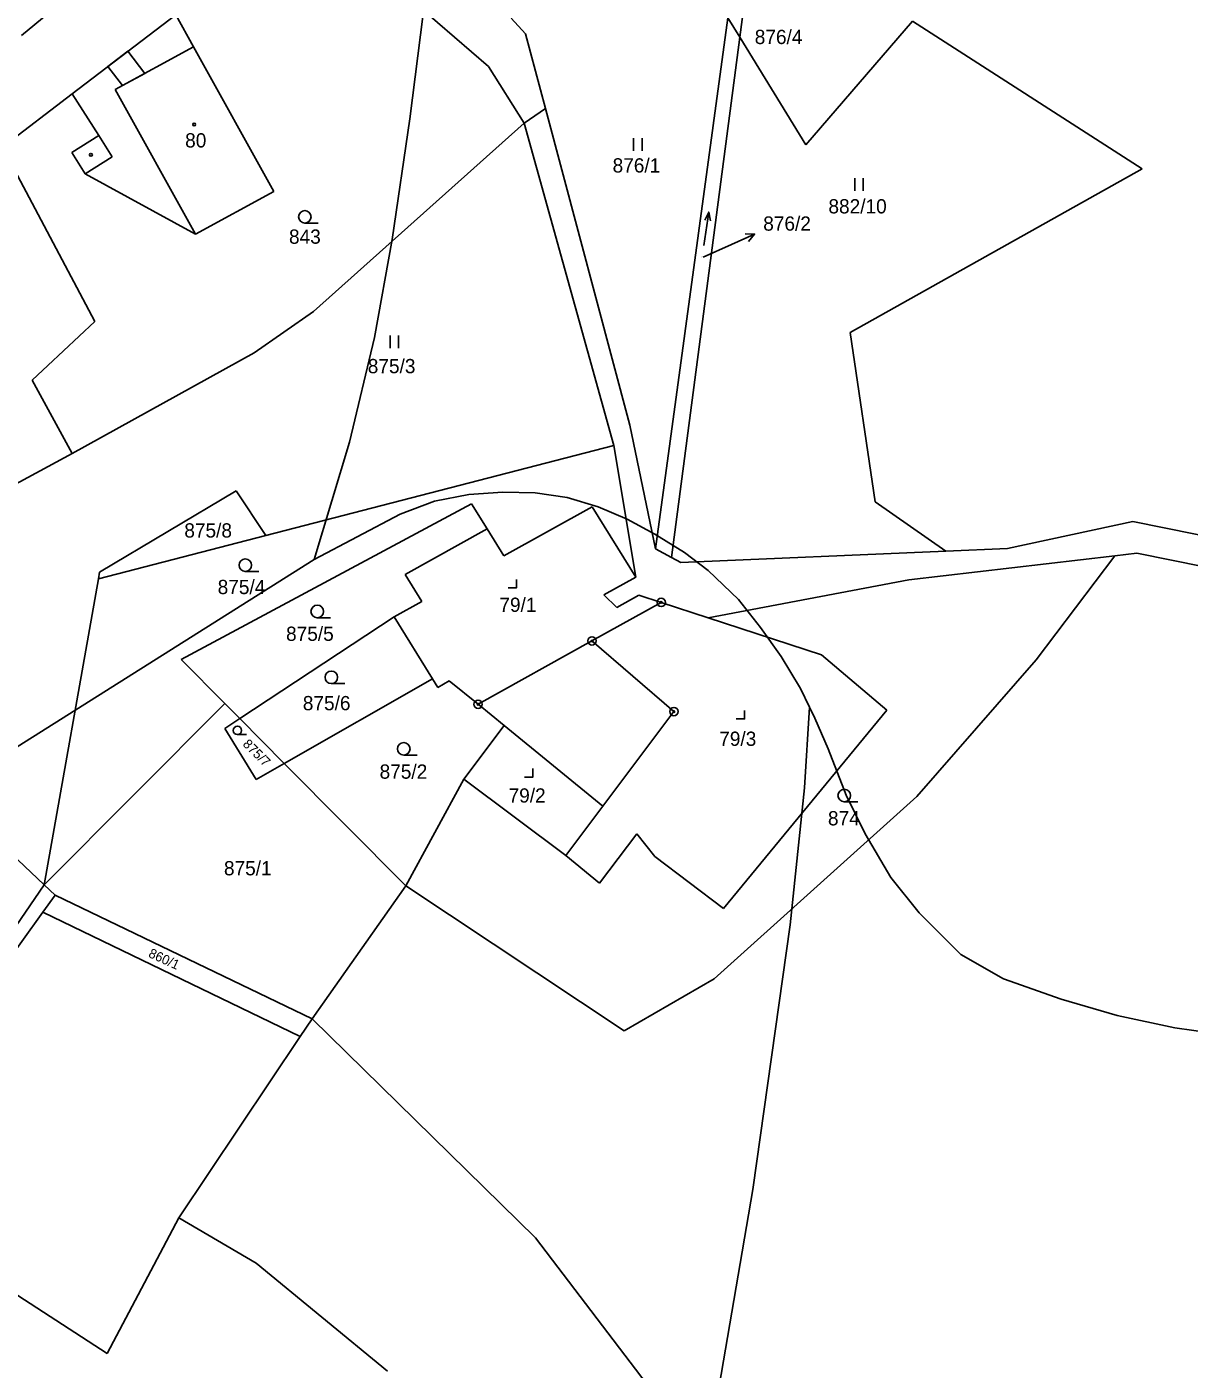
# Model space of a CAD drawing. Extents: x -546762 to -540209, y -1046851 to -1035694.
# Drawn here: x -543897 to -543758.3, y -1042074.7 to -1041914.5 of the extents above; entities that cross this region are included whole.
import ezdxf

# ---------------------------------------------------------------- set-up
doc = ezdxf.new("R2010")
doc.units = 0
for name, color, linetype in [('Vrstva 1', 7, 'Continuous'), ('Vrstva 16', 7, 'Continuous'), ('Vrstva 18', 7, 'Continuous'), ('Vrstva 19', 7, 'Continuous'), ('Vrstva 24', 7, 'Continuous'), ('Vrstva 25', 7, 'Continuous'), ('Vrstva 3', 7, 'Continuous'), ('Vrstva 30', 7, 'Continuous'), ('Vrstva 37', 7, 'Continuous'), ('Vrstva 4', 7, 'Continuous'), ('Vrstva 52', 7, 'Continuous'), ('Vrstva 6', 7, 'Continuous')]:
    doc.layers.add(name, color=color, linetype=linetype)

msp = doc.modelspace()

# ---------------------------------------------------------------- linework, layer by layer
at = {"layer": 'Vrstva 1'}
for p, q in [((-543811.96, -1041915.75), (-543810.7, -1041906.17)), ((-543813.38, -1041913.44), (-543822.02, -1041976.78)), ((-543813.38, -1041913.44), (-543811.96, -1041915.75)), ((-543804.07, -1041928.59), (-543791.36, -1041913.82)), ((-543763.94, -1041931.44), (-543791.36, -1041913.82)), ((-543820.11, -1041977.82), (-543811.96, -1041915.75)), ((-543811.96, -1041915.75), (-543804.07, -1041928.59))]:
    msp.add_line(p, q, dxfattribs=at)
for points in [[(-543847.79, -1041874.33), (-543897.64, -1041915.53)], [(-543841.93, -1041919.22), (-543852.08, -1041910.45)], [(-543879.25, -1041913.07), (-543891.6, -1041922.49)], [(-543877.12, -1041916.9), (-543879.25, -1041913.07)], [(-543837.53, -1041915.32), (-543839.22, -1041913.48)], [(-543837.53, -1041915.32), (-543835.15, -1041924.24)], [(-543877.12, -1041916.9), (-543867.53, -1041934.15)], [(-543841.93, -1041919.22), (-543837.7, -1041926.02)], [(-543891.6, -1041922.49), (-543899.92, -1041928.85)], [(-543891.6, -1041922.49), (-543888.44, -1041927.49)], [(-543837.7, -1041926.02), (-543835.15, -1041924.24)], [(-543835.15, -1041924.24), (-543825.08, -1041962.04)], [(-543837.7, -1041926.02), (-543862.8, -1041948.46)], [(-543826.99, -1041964.46), (-543837.7, -1041926.02)], [(-543888.44, -1041927.49), (-543891.66, -1041929.52)], [(-543888.91, -1041949.67), (-543899.92, -1041928.85)], [(-543891.66, -1041929.52), (-543890.05, -1041932.06)], [(-543890.05, -1041932.06), (-543876.88, -1041939.23)], [(-543867.53, -1041934.15), (-543876.88, -1041939.23)], [(-543888.91, -1041949.67), (-543896.39, -1041956.67)], [(-543862.8, -1041948.46), (-543869.88, -1041953.41)], [(-543869.88, -1041953.41), (-543891.62, -1041965.43)], [(-543896.39, -1041956.67), (-543891.62, -1041965.43)], [(-543825.08, -1041962.04), (-543822.02, -1041976.78)], [(-543826.99, -1041964.46), (-543868.49, -1041975.19)], [(-543824.36, -1041980.17), (-543826.99, -1041964.46)], [(-543891.62, -1041965.43), (-543922.35, -1041982.05)], [(-543872.05, -1041969.89), (-543888.34, -1041979.59)], [(-543872.05, -1041969.89), (-543868.49, -1041975.19)], [(-543878.6, -1041990), (-543843.97, -1041971.41)], [(-543843.97, -1041971.41), (-543842.1, -1041974.43)], [(-543840.11, -1041977.64), (-543829.56, -1041971.77)], [(-543829.56, -1041971.77), (-543824.36, -1041980.17)], [(-543780.03, -1041976.76), (-543765.06, -1041973.55)], [(-543765.06, -1041973.55), (-543735.36, -1041979.55)], [(-543868.49, -1041975.19), (-543888.48, -1041980.36)], [(-543851.87, -1041979.87), (-543842.1, -1041974.43)], [(-543842.1, -1041974.43), (-543840.11, -1041977.64)], [(-543820.11, -1041977.82), (-543822.02, -1041976.78)], [(-543818.99, -1041978.42), (-543787.37, -1041977.07)], [(-543787.37, -1041977.07), (-543780.03, -1041976.76)], [(-543818.99, -1041978.42), (-543820.11, -1041977.82)], [(-543767.21, -1041977.62), (-543791.8, -1041980.48)], [(-543776.58, -1041990.04), (-543767.21, -1041977.62)], [(-543764.58, -1041977.32), (-543767.21, -1041977.62)], [(-543764.58, -1041977.32), (-543736.23, -1041983.05)], [(-543894.94, -1042016.9), (-543888.48, -1041980.36)], [(-543888.48, -1041980.36), (-543888.34, -1041979.59)], [(-543849.89, -1041983.08), (-543851.87, -1041979.87)], [(-543824.36, -1041980.17), (-543828.16, -1041982.29)], [(-543791.8, -1041980.48), (-543815.73, -1041985.02)], [(-543853.2, -1041984.92), (-543849.89, -1041983.08)], [(-543829.59, -1041987.79), (-543821.33, -1041983.19)], [(-543826.62, -1041983.78), (-543828.16, -1041982.29)], [(-543823.99, -1041982.32), (-543826.62, -1041983.78)], [(-543821.33, -1041983.19), (-543823.99, -1041982.32)], [(-543815.73, -1041985.02), (-543821.33, -1041983.19)], [(-543871.61, -1041997.05), (-543853.2, -1041984.92)], [(-543853.2, -1041984.92), (-543848.62, -1041992.33)], [(-543815.73, -1041985.02), (-543802.2, -1041989.44)], [(-543843.18, -1041995.35), (-543829.59, -1041987.79)], [(-543829.59, -1041987.79), (-543819.81, -1041996.22)], [(-543878.6, -1041990), (-543873.39, -1041995.26)], [(-543802.2, -1041989.44), (-543794.42, -1041996.03)], [(-543790.82, -1042006.37), (-543776.58, -1041990.04)], [(-543921.63, -1041991.59), (-543894.94, -1042016.9)], [(-543866.3, -1042002.41), (-543848.62, -1041992.33)], [(-543848, -1041993.33), (-543848.62, -1041992.33)], [(-543846.61, -1041992.56), (-543848, -1041993.33)], [(-543846.61, -1041992.56), (-543843.18, -1041995.35)], [(-543894.94, -1042016.9), (-543873.39, -1041995.26)], [(-543873.39, -1041995.26), (-543871.61, -1041997.05)], [(-543843.18, -1041995.35), (-543840.08, -1041997.88)], [(-543819.81, -1041996.22), (-543828.29, -1042007.5)], [(-543794.42, -1041996.03), (-543813.9, -1042019.71)], [(-543873.4, -1041998.24), (-543871.61, -1041997.05)], [(-543871.61, -1041997.05), (-543866.3, -1042002.41)], [(-543840.08, -1041997.88), (-543844.88, -1042004.27)], [(-543873.4, -1041998.24), (-543869.64, -1042004.32)], [(-543869.64, -1042004.32), (-543866.3, -1042002.41)], [(-543866.3, -1042002.41), (-543851.8, -1042017.03)], [(-543851.8, -1042017.03), (-543844.88, -1042004.27)], [(-543844.88, -1042004.27), (-543832.73, -1042013.4)], [(-543828.29, -1042007.5), (-543832.73, -1042013.4)], [(-543790.82, -1042006.37), (-543815, -1042028.12)], [(-543828.68, -1042016.7), (-543824.24, -1042010.81)], [(-543824.24, -1042010.81), (-543822.09, -1042013.53)], [(-543832.73, -1042013.4), (-543828.68, -1042016.7)], [(-543822.09, -1042013.53), (-543813.9, -1042019.71)], [(-543902.27, -1042027.56), (-543894.94, -1042016.9)], [(-543894.94, -1042016.9), (-543893.65, -1042018.12)], [(-543862.98, -1042032.87), (-543851.8, -1042017.03)], [(-543851.8, -1042017.03), (-543825.76, -1042034.33)], [(-543895.1, -1042020.15), (-543893.65, -1042018.12)], [(-543862.98, -1042032.87), (-543893.65, -1042018.12)], [(-543900.12, -1042027.17), (-543895.1, -1042020.15)], [(-543895.1, -1042020.15), (-543864.4, -1042034.99)], [(-543825.76, -1042034.33), (-543815, -1042028.12)], [(-543862.98, -1042032.87), (-543864.4, -1042034.99)], [(-543864.4, -1042034.99), (-543878.87, -1042056.65)], [(-543887.45, -1042072.84), (-543925.56, -1042048.06)], [(-543887.45, -1042072.84), (-543878.87, -1042056.65)], [(-543878.87, -1042056.65), (-543869.64, -1042062.06)], [(-543869.64, -1042062.06), (-543853.98, -1042074.92)]]:
    msp.add_lwpolyline(points, dxfattribs=at)
at = {"layer": 'Vrstva 16'}
msp.add_line((-543812.93, -1041940.47), (-543810.19, -1041939.24), dxfattribs=at)
for points in [[(-543811.31, -1041939.19), (-543810.19, -1041939.24), (-543810.9, -1041940.11)], [(-543816.34, -1041942), (-543812.93, -1041940.47)]]:
    msp.add_lwpolyline(points, dxfattribs=at)
at = {"layer": 'Vrstva 24'}
for centre, radius in [((-543821.33, -1041983.19), 0.5), ((-543821.33, -1041983.19), 0.1), ((-543829.59, -1041987.79), 0.5), ((-543829.59, -1041987.79), 0.1), ((-543843.18, -1041995.35), 0.5), ((-543843.18, -1041995.35), 0.1), ((-543819.81, -1041996.22), 0.5), ((-543819.81, -1041996.22), 0.1)]:
    msp.add_circle(centre, radius, dxfattribs=at)
at = {"layer": 'Vrstva 25'}
for p, q in [((-543824.62, -1041929.31), (-543824.62, -1041927.81)), ((-543823.62, -1041929.31), (-543823.62, -1041927.81)), ((-543798.23, -1041934.07), (-543798.23, -1041932.57)), ((-543797.23, -1041934.07), (-543797.23, -1041932.57)), ((-543863.85, -1041937.93), (-543862.25, -1041937.93)), ((-543853.66, -1041952.84), (-543853.66, -1041951.34)), ((-543852.66, -1041952.84), (-543852.66, -1041951.34)), ((-543870.95, -1041979.5), (-543869.35, -1041979.5)), ((-543862.37, -1041985.02), (-543860.77, -1041985.02)), ((-543860.69, -1041992.88), (-543859.09, -1041992.88)), ((-543871.89, -1041998.96), (-543870.82, -1041998.96)), ((-543852.05, -1042001.41), (-543850.45, -1042001.41)), ((-543799.49, -1042006.98), (-543797.89, -1042006.98))]:
    msp.add_line(p, q, dxfattribs=at)
for points in [[(-543816.24, -1041940.59), (-543815.66, -1041936.61), (-543816.14, -1041937.56)], [(-543815.66, -1041936.61), (-543815.47, -1041937.65)], [(-543839.6, -1041981.46), (-543838.6, -1041981.46), (-543838.6, -1041980.46)], [(-543812.39, -1041997.1), (-543811.39, -1041997.1), (-543811.39, -1041996.1)], [(-543837.64, -1042004.03), (-543836.64, -1042004.03), (-543836.64, -1042003.03)]]:
    msp.add_lwpolyline(points, dxfattribs=at)
for centre, radius in [((-543877.05, -1041926.16), 0.175), ((-543889.37, -1041929.78), 0.175), ((-543863.85, -1041937.18), 0.75), ((-543870.95, -1041978.75), 0.75), ((-543862.37, -1041984.27), 0.75), ((-543860.69, -1041992.13), 0.75), ((-543871.89, -1041998.46), 0.503), ((-543852.05, -1042000.66), 0.75), ((-543799.49, -1042006.23), 0.75)]:
    msp.add_circle(centre, radius, dxfattribs=at)
at = {"layer": 'Vrstva 3'}
for points in [[(-543877.12, -1041916.9), (-543886.47, -1041921.98)], [(-543877.12, -1041916.9), (-543867.53, -1041934.15)], [(-543886.47, -1041921.98), (-543876.88, -1041939.23)], [(-543867.53, -1041934.15), (-543876.88, -1041939.23)]]:
    msp.add_lwpolyline(points, dxfattribs=at)
at = {"layer": 'Vrstva 30'}
msp.add_lwpolyline([(-543887.34, -1041919.24), (-543884.95, -1041917.42), (-543882.94, -1041920.06), (-543885.6, -1041921.51), (-543887.34, -1041919.24)], dxfattribs=at)
at = {"layer": 'Vrstva 37'}
msp.add_circle((-543877.05, -1041926.16), 0.175, dxfattribs=at)
at = {"layer": 'Vrstva 4'}
for points in [[(-543877.12, -1041916.9), (-543886.47, -1041921.98)], [(-543886.47, -1041921.98), (-543876.88, -1041939.23)], [(-543888.44, -1041927.49), (-543886.84, -1041930.03)], [(-543886.84, -1041930.03), (-543890.05, -1041932.06)], [(-543840.08, -1041997.88), (-543828.29, -1042007.5)]]:
    msp.add_lwpolyline(points, dxfattribs=at)
at = {"layer": 'Vrstva 52'}
for points in [[(-543862.75, -1041978.07), (-543858.51, -1041964.07), (-543855.54, -1041951.56), (-543853.43, -1041939.9), (-543851.31, -1041925.48), (-543849.4, -1041910.42), (-543848.13, -1041894.31), (-543846.64, -1041875.22), (-543846.58, -1041863.67), (-543846.79, -1041846.49), (-543847.85, -1041825.92), (-543848.27, -1041809.38), (-543848.06, -1041797.08), (-543847.21, -1041787.11), (-543845.31, -1041775.66), (-543842.97, -1041764.85), (-543840.01, -1041755.31), (-543836.62, -1041745.76), (-543832.97, -1041738.45), (-543802.67, -1041692.22), (-543775.11, -1041650.23), (-543757.52, -1041623.94), (-543733.6, -1041589.69)], [(-543862.75, -1041978.07), (-543852.47, -1041972.68), (-543848.39, -1041971.09), (-543844.3, -1041970.33), (-543840.22, -1041970.05), (-543836.35, -1041970.12)], [(-543836.35, -1041970.12), (-543832.54, -1041970.68), (-543828.87, -1041971.78), (-543825.41, -1041973.24), (-543822.09, -1041975.04), (-543818.56, -1041977.25), (-543815.72, -1041979.4), (-543812.12, -1041982.86), (-543809.5, -1041986.19), (-543807, -1041989.65), (-543804.72, -1041993.46), (-543803.62, -1041995.7)], [(-543983.78, -1042077.26), (-543981.6, -1042070.6), (-543978.95, -1042064.08), (-543974.1, -1042055.84), (-543968.65, -1042048.33), (-543961.15, -1042040.09), (-543955.45, -1042034.39), (-543949.52, -1042030.27), (-543944.07, -1042026.64), (-543937.89, -1042023.24), (-543929.54, -1042018.88), (-543922.39, -1042014.76), (-543911.91, -1042009.07), (-543862.75, -1041978.07)], [(-543952.56, -1042225.28), (-543947.11, -1042227.7), (-543941.06, -1042229.03), (-543934.4, -1042229.52), (-543925.19, -1042228.55), (-543914.41, -1042225.52), (-543904.72, -1042221.4), (-543894.07, -1042216.31), (-543884.38, -1042209.77), (-543872.15, -1042201.53), (-543861.73, -1042193.29), (-543854.34, -1042186.02), (-543847.32, -1042178.38), (-543842.84, -1042172.66), (-543837.63, -1042164.3), (-543832.79, -1042154), (-543828.43, -1042141.89), (-543824.67, -1042128.44), (-543820.07, -1042106.26), (-543816.92, -1042091.36), (-543810.39, -1042053.26), (-543805.94, -1042021.67), (-543804.24, -1042005.31), (-543803.62, -1041995.7)], [(-543803.62, -1041995.7), (-543802.99, -1041996.99)], [(-543802.99, -1041996.99), (-543801.4, -1042000.66), (-543799.28, -1042006.19), (-543796.98, -1042010.8), (-543793.95, -1042016.01), (-543790.56, -1042020.25), (-543785.59, -1042025.22), (-543780.51, -1042028.13), (-543773.6, -1042030.55), (-543766.94, -1042032.49), (-543760.04, -1042033.94), (-543753.26, -1042034.91)]]:
    msp.add_lwpolyline(points, dxfattribs=at)
at = {"layer": 'Vrstva 6'}
for points in [[(-543763.94, -1041931.44), (-543798.78, -1041951)], [(-543798.78, -1041951), (-543795.79, -1041971.2)], [(-543795.79, -1041971.2), (-543787.37, -1041977.07)], [(-543862.98, -1042032.87), (-543836.34, -1042059.01)], [(-543836.34, -1042059.01), (-543814.39, -1042087.86)]]:
    msp.add_lwpolyline(points, dxfattribs=at)

# ---------------------------------------------------------------- texts
at = {"layer": 'Vrstva 16'}
for s, p in [('876/4', (-543810.17, -1041916.56)), ('876/2', (-543809.16, -1041938.83))]:
    msp.add_text(s, height=1.7, dxfattribs=at).set_placement(p)
at = {"layer": 'Vrstva 18'}
for s, height, p in [('876/1', 1.7, (-543827.13, -1041931.89)), ('882/10', 1.7, (-543801.38, -1041936.77)), ('843', 1.7, (-543865.74, -1041940.39)), ('876/2', 0.1, (-543816.53, -1041942)), ('875/3', 1.7, (-543856.34, -1041955.84)), ('875/8', 1.7, (-543878.23, -1041975.45)), ('875/4', 1.7, (-543874.25, -1041982.2)), ('875/5', 1.7, (-543866.09, -1041987.78)), ('875/6', 1.7, (-543864.09, -1041996.06)), ('875/2', 1.7, (-543854.93, -1042004.23)), ('874', 1.7, (-543801.44, -1042009.8)), ('875/1', 1.7, (-543873.5, -1042015.76))]:
    msp.add_text(s, height=height, dxfattribs=at).set_placement(p)
for s, rotation, p in [('875/7', 315.089, (-543871.34, -1042000.19)), ('860/1', 335.3242, (-543882.6, -1042025.46))]:
    msp.add_text(s, height=1.14, rotation=rotation, dxfattribs=at).set_placement(p)
at = {"layer": 'Vrstva 19'}
for s, p in [('80', (-543878.13, -1041928.9)), ('79/1', (-543840.64, -1041984.32)), ('79/3', (-543814.41, -1042000.31)), ('79/2', (-543839.54, -1042007.08))]:
    msp.add_text(s, height=1.7, dxfattribs=at).set_placement(p)

doc.saveas('drawing.dxf')
